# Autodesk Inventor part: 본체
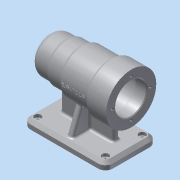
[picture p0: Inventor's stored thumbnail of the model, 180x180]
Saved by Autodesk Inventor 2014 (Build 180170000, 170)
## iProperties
Created: 2016-06
Part Number: 본체
Material: 알루미늄 6061
Document SubType Name: Modeling
Designer: SCD-A15
Density: 2.71 g/cm^3
Appearance: 알루미늄 - 평지
Mass: 672.417 g
Surface Area: 647.545 cm^2
Volume: 248.124 cm^3
Author: SCD-A15
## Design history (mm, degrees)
sketch "스케치1"
  geometry: L1 (0, 0)-(112, 0); L2 (0, 0)-(0, 25); L3 (0, 25)-(25, 25); L4 (25, 25)-(25, 27); L5 (25, 27)-(45, 27); L6 (45, 27)-(45, 30); L7 (112, 0)-(112, 34); L8 (112, 34)-(84, 34); L9 (84, 34)-(84, 30); L10 (84, 30)-(45, 30); L11 (112, 21)-(97, 21); L12 (97, 21)-(97, 21); L13 (94, 24)-(43, 24); L14 (43, 24)-(43, 21); L15 (43, 21)-(31, 21); L16 (31, 21)-(31, 17.5); L17 (31, 17.5)-(13, 17.5); L18 (13, 17.5)-(13, 16); L19 (13, 16)-(9, 16); L20 (9, 16)-(9, 10.5); L21 (9, 10.5)-(6, 10.5); L22 (6, 10.5)-(6, 0); A1 r 3 centre (94, 21) between (97, 21) and (94, 24); 1 further point
  constraints: 44 end point, 10 parallel, 10 perpendicular, 4 point on line, 2 point on circle, 2 tangent, 1 centre point, 1 collinear, 1 horizontal
  dimensions: "d0" = 50 diameter of L3 L1; "d1" = 54 diameter of L5 L1; "d2" = 60 diameter of L10 L1; "d3" = 68 diameter of L8 L1; "d4" = 112 distance of L1.start L1.end; "d5" = 84 distance between parallel lines of L2 L9; "d6" = 45 distance between parallel lines of L2 L6; "d7" = 25 distance between parallel lines of L2 L4; "d8" = 42 diameter of L11 L1; "d9" = 48 diameter of L13 L1; "d10" = 42 diameter of L15 L1; "d11" = 35 diameter of L17 L1; "d12" = 32 diameter of L19 L1; "d14" = 15 distance between parallel lines of L7 L12; "d15" = 54 distance between parallel lines of L12 L14; "d16" = 18 distance between parallel lines of L16 L18; "d17" = 12 distance between parallel lines of L14 L16; "d47" = 21 diameter of L21 L1; "d48" = 3 distance between parallel lines of L20 L22; "d49" = 4 distance between parallel lines of L18 L20; "d79" = 3 radius of A1
revolve "회전1" sketch "스케치1" stored, may be unused: angle "d18" = 90 deg
sketch "스케치2"
  geometry: L1 (0, -60)-(112, -60); L2 (112, -60)-(112, -70); L3 (112, -70)-(0, -70); L4 (0, -70)-(0, -60); L5 (112, -21)-(112, 21) reference; L6 (0, 0)-(112, 0); 2 further points
  constraints: 10 end point, 3 midpoint, 2 parallel, 1 horizontal, 1 perpendicular, 1 vertical alignment
  dimensions: "d19" = 70 distance between parallel lines of L3 L6; "d20" = 10 distance of L1.end L2.end; "d21" = 112 distance of L2.end L3.end
extrude "돌출1" join sketch "스케치2" stored distance "d22" = 70; taper "d23" = 0 deg
sketch "스케치3"
  geometry: L1 (0, 70)-(0, 0) reference; L2 (0, 70)-(112, 70) reference; L3 (20, 39)-(92, 39); L4 (92, 39)-(92, 31); L5 (92, 31)-(20, 31); L6 (20, 31)-(20, 39); 5 further points
  constraints: 8 end point, 4 midpoint, 2 parallel, 1 horizontal, 1 horizontal alignment, 1 perpendicular, 1 vertical alignment
  dimensions: "d24" = 20 distance between parallel lines of L6 L1; "d25" = 8 distance of L3.end L4.end
extrude "돌출2" join sketch "스케치3" stored distance "d26" = 70; taper "d27" = 0 deg
node "작업 평면1"
sketch "스케치4"
  geometry: L1 (-70, 10)-(0, 10) reference; L2 (-19.491, 44.32)-(-7, 10); L3 (-50.509, 44.32)-(-63, 10); A1 r 30 centre (-35, 70) between (-31, 40.268) and (-39, 40.268) reference; 1 further point
  constraints: 4 end point, 2 point on circle, 2 point on line
  dimensions: "d28" = 7 distance of L1.end L2.end; "d29" = 7 distance of L1.start L3.end; "d30" = 110 deg angle of L1 L2; "d31" = 110 deg angle of L1 L3
extrude "돌출3" join sketch "스케치4" stored distance "d32" = 8; taper "d33" = 0 deg
sketch "스케치5"
  geometry: C1 r 34 at (0, 0) reference; 1 further point
  constraints: 1 vertical alignment
  dimensions: "d34" = 26 distance of C1.centre point (0, 26)
hole "구멍1" sketch "스케치5" at (0, 26) diameter "d35" = 3.242; stored, may be unused: countersink angle "d39" = 90 deg, drill point angle "d41" = 118 deg; dims "d36" = 8, "d37" = 4, "d38" = 2, "d40" = 11
sketch "스케치6"
  geometry: C1 r 24 at (0, 0) reference; C2 r 24 at (0, 0)
  constraints: 1 centre point, 1 coincident, 1 concentric
extrude "돌출4" cut sketch "스케치6" distance "d45" = 8; taper "d46" = 0 deg
fillet "모깎기1" dims "d50" = 3
fillet "모깎기2" dims "d51" = 0.3
fillet "모깎기4" dims "d53" = 10
fillet "모깎기5" dims "d54" = 3
fillet "모깎기6" dims "d55" = 3
sketch "스케치7"
  geometry: L1 (52, 63)-(60, 63) reference; L2 (112, 0)-(0, 0) reference; L3 (112, 0)-(112, 70) reference; L4 (0, 70)-(112, 70) reference; L5 (9.974, 60)-(101.974, 60); L6 (101.974, 60)-(101.974, 10); L7 (101.974, 10)-(10.026, 10); 7 further points
  constraints: 6 end point, 6 midpoint, 2 parallel, 2 vertical alignment, 1 horizontal alignment, 1 perpendicular
  dimensions: "d56" = 92 distance of L5.start L5.end; "d57" = 50 distance of L5.end L6.end
hole "구멍2" sketch "스케치7" at (9.974, 60), (101.974, 60), (101.974, 10), (10.026, 10) diameter "d58" = 5; stored, may be unused: countersink angle "d62" = 90 deg, drill point angle "d64" = 118 deg; dims "d59" = 8, "d60" = 9, "d61" = 4, "d63" = 11
fillet "모깎기7" dims "d65" = 10
fillet "모깎기8" dims "d66" = 3
fillet "모깎기9" dims "d67" = 3
chamfer "모따기1" distance "d68" = 1; stored, may be unused: second distance "d69" = 2, angle "d70" = 45 deg
chamfer "모따기2" distance "d71" = 4; stored, may be unused: second distance "d72" = 2, angle "d73" = 45 deg
node "작업 평면2"
sketch "스케치8"
  geometry: L1 (112, -34)-(112, 34) reference; 2 further points
  constraints: 1 horizontal alignment, 1 other
  dimensions: "d75" = 48 distance from line of L1 point (64, 0)
feature "엠보싱1" sketch "스케치8" dims "d76" = 0.5, "d77" = 0
fillet "모깎기10" dims "d78" = 3
node "솔리드1"
pattern_circular "원형 패턴1" dims angle "d43" = 360 deg
other parameters: "d74" = 2
